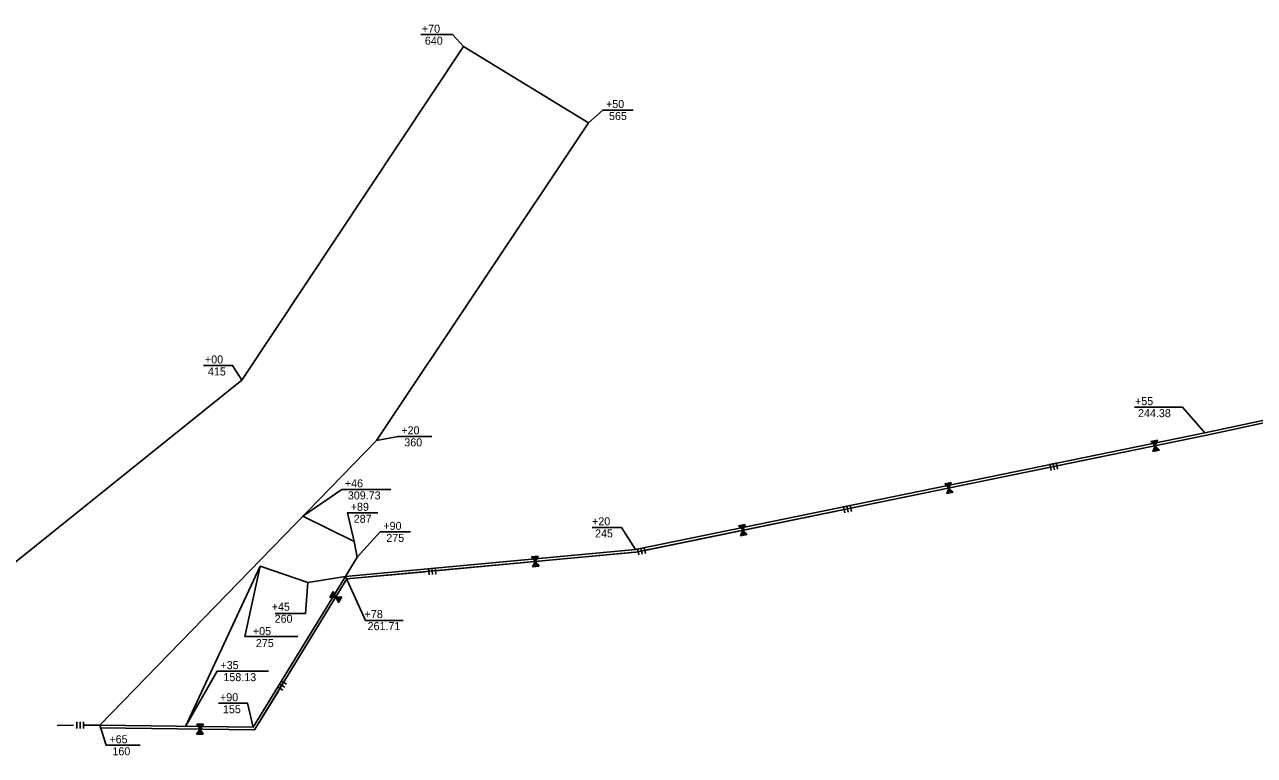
# Model space of a CAD drawing. Extents: x 979729 to 993523, y 1834148 to 1845433.
# Drawn here: x 984124 to 985045, y 1837862 to 1838409 of the extents above; entities that cross this region are included whole.
import ezdxf

# ---------------------------------------------------------------- set-up
doc = ezdxf.new("R2010")
doc.units = 0
for name, color, linetype in [('42', 7, 'Continuous'), ('51', 7, 'Continuous'), ('53', 7, 'Continuous'), ('R_Draft', 7, 'Continuous')]:
    doc.layers.add(name, color=color, linetype=linetype)

msp = doc.modelspace()

# ---------------------------------------------------------------- linework, layer by layer
at = {"layer": '42'}
for p, q in [((985008.43, 1838101.52), (985091.38, 1838119.28)), ((984582.18, 1838014.16), (985008.43, 1838101.52)), ((984967.67, 1838097), (984970.88, 1838093.83)), ((984967.74, 1838096.96), (984967.76, 1838097.02)), ((984967.94, 1838096.78), (984968.06, 1838097.08)), ((984968.12, 1838096.57), (984968.35, 1838097.14)), ((984968.33, 1838096.4), (984968.65, 1838097.2)), ((984968.51, 1838096.19), (984968.94, 1838097.26)), ((984968.7, 1838095.99), (984969.24, 1838097.32)), ((984968.89, 1838095.81), (984969.53, 1838097.38)), ((984969.12, 1838095.7), (984969.76, 1838097.28)), ((984969.18, 1838089.65), (984970.88, 1838093.83)), ((984969.29, 1838095.46), (984970.12, 1838097.5)), ((984969.49, 1838095.29), (984970.41, 1838097.56)), ((984969.66, 1838095.05), (984970.71, 1838097.62)), ((984969.88, 1838094.91), (984971, 1838097.68)), ((984970.05, 1838094.67), (984971.3, 1838097.74)), ((984970.06, 1838091.7), (984971.63, 1838090.15)), ((984970.18, 1838091.94), (984971.92, 1838090.21)), ((984970.24, 1838092.22), (984972.21, 1838090.27)), ((984970.25, 1838094.5), (984971.59, 1838097.8)), ((984970.38, 1838092.44), (984972.51, 1838090.33)), ((984970.43, 1838094.29), (984971.88, 1838097.86)), ((984970.45, 1838092.72), (984972.8, 1838090.39)), ((984970.56, 1838092.96), (984973.1, 1838090.45)), ((984970.64, 1838094.14), (984972.18, 1838097.92)), ((984970.65, 1838093.23), (984973.39, 1838090.51)), ((984970.79, 1838093.44), (984973.69, 1838090.57)), ((984970.82, 1838093.91), (984972.47, 1838097.98)), ((984970.86, 1838093.73), (984973.98, 1838090.63)), ((984970.88, 1838093.83), (984972.57, 1838098)), ((984970.88, 1838093.83), (984974.08, 1838090.65)), ((984969.22, 1838089.71), (984969.27, 1838089.67)), ((984969.34, 1838089.95), (984969.57, 1838089.73)), ((984969.43, 1838090.22), (984969.86, 1838089.79)), ((984969.55, 1838090.45), (984970.15, 1838089.85)), ((984969.63, 1838090.72), (984970.45, 1838089.91)), ((984969.72, 1838090.98), (984970.74, 1838089.97)), ((984969.84, 1838091.22), (984971.04, 1838090.03)), ((984970, 1838091.41), (984971.21, 1838090.21)), ((984892, 1838080.21), (984893.01, 1838075.31)), ((984894.45, 1838080.71), (984895.46, 1838075.82)), ((984896.9, 1838081.22), (984897.9, 1838076.32)), ((984813.38, 1838065.37), (984816.58, 1838062.2)), ((984813.45, 1838065.33), (984813.47, 1838065.39)), ((984813.65, 1838065.16), (984813.77, 1838065.45)), ((984813.83, 1838064.95), (984814.06, 1838065.51)), ((984814.03, 1838064.78), (984814.36, 1838065.57)), ((984814.22, 1838064.57), (984814.65, 1838065.63)), ((984814.4, 1838064.36), (984814.94, 1838065.69)), ((984814.6, 1838064.19), (984815.24, 1838065.75)), ((984814.83, 1838064.08), (984815.47, 1838065.66)), ((984815, 1838063.83), (984815.83, 1838065.87)), ((984815.2, 1838063.66), (984816.12, 1838065.94)), ((984815.37, 1838063.43), (984816.42, 1838066)), ((984815.58, 1838063.28), (984816.71, 1838066.06)), ((984815.76, 1838063.05), (984817, 1838066.12)), ((984815.96, 1838062.88), (984817.3, 1838066.18)), ((984816.14, 1838062.67), (984817.59, 1838066.24)), ((984816.35, 1838062.52), (984817.89, 1838066.3)), ((984816.53, 1838062.29), (984818.18, 1838066.36)), ((984816.58, 1838062.2), (984818.28, 1838066.38)), ((984814.89, 1838058.03), (984816.58, 1838062.2)), ((984814.93, 1838058.09), (984814.98, 1838058.04)), ((984815.05, 1838058.33), (984815.27, 1838058.11)), ((984815.13, 1838058.59), (984815.57, 1838058.17)), ((984815.25, 1838058.83), (984815.86, 1838058.23)), ((984815.34, 1838059.09), (984816.16, 1838058.29)), ((984815.43, 1838059.36), (984816.45, 1838058.35)), ((984815.54, 1838059.6), (984816.74, 1838058.41)), ((984815.71, 1838059.79), (984816.92, 1838058.58)), ((984815.77, 1838060.08), (984817.33, 1838058.53)), ((984815.88, 1838060.31), (984817.63, 1838058.59)), ((984815.95, 1838060.6), (984817.92, 1838058.65)), ((984816.09, 1838060.82), (984818.22, 1838058.71)), ((984816.16, 1838061.1), (984818.51, 1838058.77)), ((984816.27, 1838061.34), (984818.8, 1838058.83)), ((984816.36, 1838061.6), (984819.1, 1838058.89)), ((984816.5, 1838061.82), (984819.39, 1838058.95)), ((984816.56, 1838062.1), (984819.69, 1838059.01)), ((984816.58, 1838062.2), (984819.78, 1838059.03)), ((984737.71, 1838048.59), (984738.71, 1838043.69)), ((984740.16, 1838049.09), (984741.16, 1838044.19)), ((984742.61, 1838049.59), (984743.61, 1838044.69)), ((984659.09, 1838033.75), (984662.29, 1838030.58)), ((984659.15, 1838033.71), (984659.18, 1838033.77)), ((984659.36, 1838033.54), (984659.47, 1838033.83)), ((984659.54, 1838033.33), (984659.77, 1838033.89)), ((984659.74, 1838033.16), (984660.06, 1838033.95)), ((984659.92, 1838032.95), (984660.36, 1838034.01)), ((984660.11, 1838032.74), (984660.65, 1838034.07)), ((984660.31, 1838032.57), (984660.95, 1838034.13)), ((984660.53, 1838032.45), (984661.18, 1838034.04)), ((984660.59, 1838026.4), (984662.29, 1838030.58)), ((984660.71, 1838032.21), (984661.53, 1838034.25)), ((984660.91, 1838032.04), (984661.83, 1838034.31)), ((984660.96, 1838027.21), (984661.57, 1838026.6)), ((984661.05, 1838027.47), (984661.86, 1838026.66)), ((984661.08, 1838031.8), (984662.12, 1838034.37)), ((984661.14, 1838027.73), (984662.16, 1838026.72)), ((984661.25, 1838027.97), (984662.45, 1838026.78)), ((984661.29, 1838031.66), (984662.42, 1838034.43)), ((984661.41, 1838028.16), (984662.63, 1838026.96)), ((984661.46, 1838031.42), (984662.71, 1838034.49)), ((984661.48, 1838028.45), (984663.04, 1838026.9)), ((984661.59, 1838028.69), (984663.34, 1838026.96)), ((984661.66, 1838031.25), (984663.01, 1838034.55)), ((984661.66, 1838028.98), (984663.63, 1838027.02)), ((984661.8, 1838029.19), (984663.92, 1838027.08)), ((984661.85, 1838031.04), (984663.3, 1838034.61)), ((984661.86, 1838029.48), (984664.22, 1838027.15)), ((984661.98, 1838029.71), (984664.51, 1838027.21)), ((984662.06, 1838030.9), (984663.59, 1838034.67)), ((984662.07, 1838029.98), (984664.81, 1838027.27)), ((984662.2, 1838030.19), (984665.1, 1838027.33)), ((984662.23, 1838030.66), (984663.89, 1838034.73)), ((984662.27, 1838030.48), (984665.39, 1838027.39)), ((984662.29, 1838030.58), (984663.99, 1838034.75)), ((984662.29, 1838030.58), (984665.49, 1838027.41)), ((984588.32, 1838017.97), (984589.32, 1838013.07)), ((984660.64, 1838026.47), (984660.69, 1838026.42)), ((984660.76, 1838026.7), (984660.98, 1838026.48)), ((984660.84, 1838026.97), (984661.27, 1838026.54)), ((984365.81, 1837994.07), (984582.18, 1838014.16)), ((984503.94, 1838010.66), (984506.78, 1838007.16)), ((984504.01, 1838010.61), (984504.04, 1838010.67)), ((984504.19, 1838010.42), (984504.34, 1838010.7)), ((984504.35, 1838010.19), (984504.63, 1838010.72)), ((984504.53, 1838010), (984504.93, 1838010.75)), ((984504.69, 1838009.77), (984505.23, 1838010.78)), ((984504.85, 1838009.54), (984505.53, 1838010.81)), ((984505.03, 1838009.35), (984505.83, 1838010.84)), ((984505.24, 1838009.21), (984506.05, 1838010.72)), ((984505.38, 1838008.95), (984506.43, 1838010.89)), ((984505.56, 1838008.76), (984506.73, 1838010.92)), ((984505.71, 1838008.51), (984507.03, 1838010.95)), ((984505.9, 1838008.34), (984507.33, 1838010.98)), ((984506.05, 1838008.09), (984507.63, 1838011)), ((984506.23, 1838007.9), (984507.93, 1838011.03)), ((984506.39, 1838007.67), (984508.22, 1838011.06)), ((984506.59, 1838007.5), (984508.52, 1838011.09)), ((984506.73, 1838007.25), (984508.82, 1838011.11)), ((984506.78, 1838007.16), (984508.92, 1838011.12)), ((984583.42, 1838016.96), (984584.42, 1838012.07)), ((984585.87, 1838017.47), (984586.87, 1838012.57)), ((984426.89, 1838002.25), (984427.35, 1837997.27)), ((984429.38, 1838002.48), (984429.84, 1837997.5)), ((984431.87, 1838002.71), (984432.33, 1837997.74)), ((984504.64, 1838003.19), (984506.78, 1838007.16)), ((984504.69, 1838003.25), (984504.73, 1838003.2)), ((984504.83, 1838003.48), (984505.03, 1838003.23)), ((984504.95, 1838003.73), (984505.33, 1838003.26)), ((984505.09, 1838003.95), (984505.63, 1838003.28)), ((984505.2, 1838004.21), (984505.93, 1838003.31)), ((984505.32, 1838004.46), (984506.23, 1838003.34)), ((984505.46, 1838004.68), (984506.53, 1838003.37)), ((984505.64, 1838004.85), (984506.72, 1838003.53)), ((984505.74, 1838005.14), (984507.12, 1838003.42)), ((984505.88, 1838005.36), (984507.42, 1838003.45)), ((984505.98, 1838005.63), (984507.72, 1838003.48)), ((984506.14, 1838005.83), (984508.02, 1838003.51)), ((984506.24, 1838006.11), (984508.32, 1838003.53)), ((984506.38, 1838006.33), (984508.62, 1838003.56)), ((984506.49, 1838006.59), (984508.92, 1838003.59)), ((984506.65, 1838006.79), (984509.22, 1838003.62)), ((984506.75, 1838007.06), (984509.52, 1838003.65)), ((984506.78, 1838007.16), (984509.62, 1838003.66)), ((984296.72, 1837880.98), (984365.81, 1837994.07)), ((984353.88, 1837980.38), (984353.52, 1837981.15)), ((984354.16, 1837980.37), (984353.68, 1837981.41)), ((984354.44, 1837980.36), (984353.84, 1837981.67)), ((984354.7, 1837980.39), (984353.99, 1837981.92)), ((984354.94, 1837980.48), (984354.22, 1837982.03)), ((984355.23, 1837980.44), (984354.31, 1837982.44)), ((984355.5, 1837980.47), (984354.46, 1837982.69)), ((984355.79, 1837980.43), (984354.62, 1837982.95)), ((984356.04, 1837980.49), (984354.78, 1837983.21)), ((984356.33, 1837980.46), (984354.93, 1837983.46)), ((984356.59, 1837980.48), (984355.09, 1837983.72)), ((984356.87, 1837980.48), (984355.25, 1837983.97)), ((984357.12, 1837980.53), (984355.4, 1837984.23)), ((984357.41, 1837980.5), (984355.56, 1837984.49)), ((984357.51, 1837980.48), (984355.61, 1837984.57)), ((984353, 1837980.3), (984357.51, 1837980.48)), ((984353.08, 1837980.32), (984353.05, 1837980.38)), ((984353.34, 1837980.35), (984353.21, 1837980.64)), ((984353.62, 1837980.35), (984353.37, 1837980.9)), ((984357.51, 1837980.48), (984362.01, 1837980.66)), ((984359.4, 1837976.39), (984357.51, 1837980.48)), ((984357.57, 1837980.4), (984361.96, 1837980.58)), ((984357.73, 1837980.16), (984361.8, 1837980.32)), ((984357.79, 1837979.91), (984361.65, 1837980.06)), ((984357.93, 1837979.67), (984361.49, 1837979.81)), ((984358.02, 1837979.42), (984361.33, 1837979.55)), ((984358.18, 1837979.18), (984361.18, 1837979.3)), ((984358.25, 1837978.93), (984361.02, 1837979.04)), ((984358.41, 1837978.68), (984360.86, 1837978.78)), ((984358.5, 1837978.44), (984360.71, 1837978.53)), ((984358.68, 1837978.19), (984360.38, 1837978.26)), ((984358.7, 1837977.95), (984360.39, 1837978.01)), ((984358.8, 1837977.7), (984360.24, 1837977.76)), ((984358.93, 1837977.45), (984360.08, 1837977.5)), ((984359.07, 1837977.21), (984359.92, 1837977.24)), ((984359.16, 1837976.96), (984359.77, 1837976.99)), ((984359.29, 1837976.72), (984359.61, 1837976.73)), ((984359.39, 1837976.47), (984359.45, 1837976.47)), ((984316.28, 1837917.78), (984320.54, 1837915.18)), ((984313.67, 1837913.52), (984317.94, 1837910.91)), ((984314.97, 1837915.65), (984319.24, 1837913.04)), ((984163.63, 1837887.02), (984163.65, 1837882.02)), ((984166.13, 1837887.03), (984166.15, 1837882.03)), ((984168.63, 1837887.04), (984168.65, 1837882.04)), ((984180.83, 1837882.6), (984296.72, 1837880.98)), ((984253.28, 1837877.84), (984255.83, 1837881.55)), ((984253.38, 1837885.34), (984255.83, 1837881.55)), ((984253.44, 1837885.28), (984253.47, 1837885.33)), ((984253.6, 1837885.07), (984253.77, 1837885.33)), ((984253.73, 1837884.83), (984254.07, 1837885.33)), ((984253.89, 1837884.61), (984254.38, 1837885.32)), ((984254.02, 1837884.37), (984254.68, 1837885.32)), ((984254.16, 1837884.13), (984254.98, 1837885.31)), ((984254.32, 1837883.92), (984255.28, 1837885.31)), ((984254.51, 1837883.76), (984255.48, 1837885.17)), ((984254.63, 1837883.48), (984255.88, 1837885.3)), ((984254.74, 1837879.86), (984256.07, 1837877.8)), ((984254.79, 1837883.27), (984256.18, 1837885.3)), ((984254.87, 1837880.12), (984256.37, 1837877.79)), ((984254.91, 1837883.01), (984256.48, 1837885.29)), ((984255.05, 1837880.3), (984256.67, 1837877.79)), ((984255.08, 1837882.82), (984256.78, 1837885.29)), ((984255.17, 1837880.57), (984256.97, 1837877.78)), ((984255.2, 1837882.55), (984257.08, 1837885.28)), ((984255.34, 1837880.77), (984257.27, 1837877.78)), ((984255.36, 1837882.34), (984257.38, 1837885.28)), ((984255.48, 1837881.01), (984257.57, 1837877.78)), ((984255.5, 1837882.1), (984257.68, 1837885.27)), ((984255.66, 1837881.19), (984257.88, 1837877.77)), ((984255.67, 1837881.91), (984257.98, 1837885.27)), ((984255.79, 1837881.64), (984258.28, 1837885.27)), ((984255.79, 1837881.46), (984258.18, 1837877.77)), ((984255.83, 1837881.55), (984258.38, 1837885.27)), ((984255.83, 1837881.55), (984258.28, 1837877.77)), ((984253.33, 1837877.89), (984253.37, 1837877.83)), ((984253.5, 1837878.1), (984253.67, 1837877.83)), ((984253.64, 1837878.34), (984253.97, 1837877.83)), ((984253.81, 1837878.54), (984254.27, 1837877.82)), ((984253.95, 1837878.78), (984254.57, 1837877.82)), ((984254.09, 1837879.02), (984254.87, 1837877.81)), ((984254.25, 1837879.23), (984255.17, 1837877.81)), ((984254.45, 1837879.38), (984255.38, 1837877.95)), ((984254.58, 1837879.65), (984255.77, 1837877.8))]:
    msp.add_line(p, q, dxfattribs=at)
for points in [[(984897.4, 1838078.77), (985008.43, 1838101.52), (985044.28, 1838109.2)], [(984967.67, 1838097), (984972.57, 1838098)], [(984969.18, 1838089.65), (984974.08, 1838090.65)], [(984743.11, 1838047.14), (984890.06, 1838077.26)], [(984813.38, 1838065.37), (984818.28, 1838066.38)], [(984814.89, 1838058.03), (984819.78, 1838059.03)], [(984588.82, 1838015.52), (984735.76, 1838045.64)], [(984659.09, 1838033.75), (984663.99, 1838034.75)], [(984660.59, 1838026.4), (984665.49, 1838027.41)], [(984432.1, 1838000.22), (984581.46, 1838014.09)], [(984503.94, 1838010.66), (984508.92, 1838011.12)], [(984318.41, 1837916.48), (984365.81, 1837994.07), (984424.63, 1837999.53)], [(984504.64, 1838003.19), (984509.62, 1838003.66)], [(984353, 1837980.3), (984355.61, 1837984.57)], [(984359.4, 1837976.39), (984362.01, 1837980.66)], [(984180.83, 1837882.6), (984296.72, 1837880.98), (984314.5, 1837910.08)], [(984148.76, 1837884.45), (984161.14, 1837884.51)], [(984168.64, 1837884.54), (984180.84, 1837884.6)], [(984253.38, 1837885.34), (984258.38, 1837885.27)], [(984253.28, 1837877.84), (984258.28, 1837877.77)]]:
    msp.add_lwpolyline(points, dxfattribs=at)
at = {"layer": '51'}
msp.add_lwpolyline([(983839.63, 1837883.59), (983964.23, 1837883.62), (984287.23, 1838143), (984453.05, 1838392.87), (984546.56, 1838335.6), (984387.83, 1838097.74), (984180.84, 1837884.6), (984295.61, 1837882.99), (984364.62, 1837995.97), (984581.88, 1838016.14), (985008.02, 1838103.48), (985091.14, 1838121.27)], dxfattribs=at)
at = {"layer": '53'}
for points in [[(984332.75, 1838041.03), (984371.18, 1838022.15), (984373.39, 1838010.33)], [(984373.39, 1838010.33), (984364.62, 1837995.97), (984336.44, 1837991.43), (984300.95, 1838003.61), (984245.03, 1837883.7)]]:
    msp.add_lwpolyline(points, dxfattribs=at)
at = {"layer": 'R_Draft'}
for p, q in [((984421.06, 1838401.8), (984438.94, 1838401.8)), ((984563.4, 1838345.26), (984580.16, 1838345.26)), ((984258.41, 1838153.96), (984274.21, 1838153.96)), ((984955.49, 1838122.75), (984985.3, 1838122.75)), ((984410.15, 1838100.87), (984429.47, 1838100.87)), ((984367.88, 1838061.16), (984398.6, 1838061.16)), ((984372.28, 1838043.63), (984389.04, 1838043.63)), ((984396.69, 1838029.36), (984413.45, 1838029.36)), ((984549.46, 1838032.72), (984565.26, 1838032.72)), ((984312.06, 1837968.26), (984328.82, 1837968.26)), ((984407.99, 1837963.03), (984385.83, 1837963.03)), ((984295.37, 1837950.98), (984329.14, 1837950.98)), ((984274.73, 1837925.05), (984306.99, 1837925.05)), ((984269.67, 1837901.04), (984285.47, 1837901.04)), ((984191.62, 1837869.53), (984210.94, 1837869.53))]:
    msp.add_line(p, q, dxfattribs=at)
for points in [[(984453.05, 1838392.87), (984444.94, 1838401.8), (984438.94, 1838401.8)], [(984546.56, 1838335.6), (984557.4, 1838345.26), (984563.4, 1838345.26)], [(984287.23, 1838143), (984280.21, 1838153.96), (984274.21, 1838153.96)], [(985008.02, 1838103.48), (984991.3, 1838122.75), (984985.3, 1838122.75)], [(984387.83, 1838097.74), (984404.15, 1838100.87), (984410.15, 1838100.87)], [(984332.75, 1838041.03), (984361.88, 1838061.16), (984367.88, 1838061.16)], [(984371.18, 1838022.15), (984366.28, 1838043.63), (984372.28, 1838043.63)], [(984373.39, 1838010.33), (984390.69, 1838029.36), (984396.69, 1838029.36)], [(984581.88, 1838016.14), (984571.26, 1838032.72), (984565.26, 1838032.72)], [(984300.95, 1838003.61), (984289.37, 1837950.98), (984295.37, 1837950.98)], [(984336.44, 1837991.43), (984334.82, 1837968.26), (984328.82, 1837968.26)], [(984364.62, 1837995.97), (984379.83, 1837963.03), (984385.83, 1837963.03)], [(984245.03, 1837883.7), (984268.73, 1837925.05), (984274.73, 1837925.05)], [(984295.61, 1837882.99), (984291.47, 1837901.04), (984285.47, 1837901.04)], [(984180.84, 1837884.6), (984185.62, 1837869.53), (984191.62, 1837869.53)]]:
    msp.add_lwpolyline(points, dxfattribs=at)

# ---------------------------------------------------------------- texts
for s, p in [('+70', (984421.93, 1838403.15)), (' 640', (984421.93, 1838394.15)), ('+50', (984559.78, 1838346.76)), (' 565', (984559.78, 1838337.76)), ('+00', (984259.5, 1838155.46)), (' 415', (984259.5, 1838146.46)), ('+55', (984955.87, 1838124.25)), (' 244.38', (984955.87, 1838115.25)), ('+20', (984406.53, 1838102.37)), (' 360', (984406.53, 1838093.37)), ('+46', (984364.26, 1838062.66)), (' 309.73', (984364.26, 1838053.66)), ('+89', (984368.66, 1838045.13)), (' 287', (984368.66, 1838036.13)), ('+90', (984393.06, 1838030.86)), ('+20', (984549.35, 1838034.22)), (' 275', (984393.06, 1838021.86)), (' 245', (984549.35, 1838025.22)), ('+45', (984309.46, 1837970.28)), (' 260', (984309.46, 1837961.28)), ('+78', (984379.03, 1837964.79)), ('+05', (984295.4, 1837952.07)), (' 261.71', (984379.03, 1837955.79)), (' 275', (984295.4, 1837943.07)), ('+90', (984270.76, 1837902.54)), (' 155', (984270.76, 1837893.54)), ('+65', (984188, 1837871.03)), (' 160', (984188, 1837862.03))]:
    msp.add_text(s, height=6, rotation=360, dxfattribs=at).set_placement(p)
for s, p in [('+35', (984271.1, 1837926.55)), (' 158.13', (984271.1, 1837917.55))]:
    msp.add_text(s, height=6, dxfattribs=at).set_placement(p)

doc.saveas('drawing.dxf')
